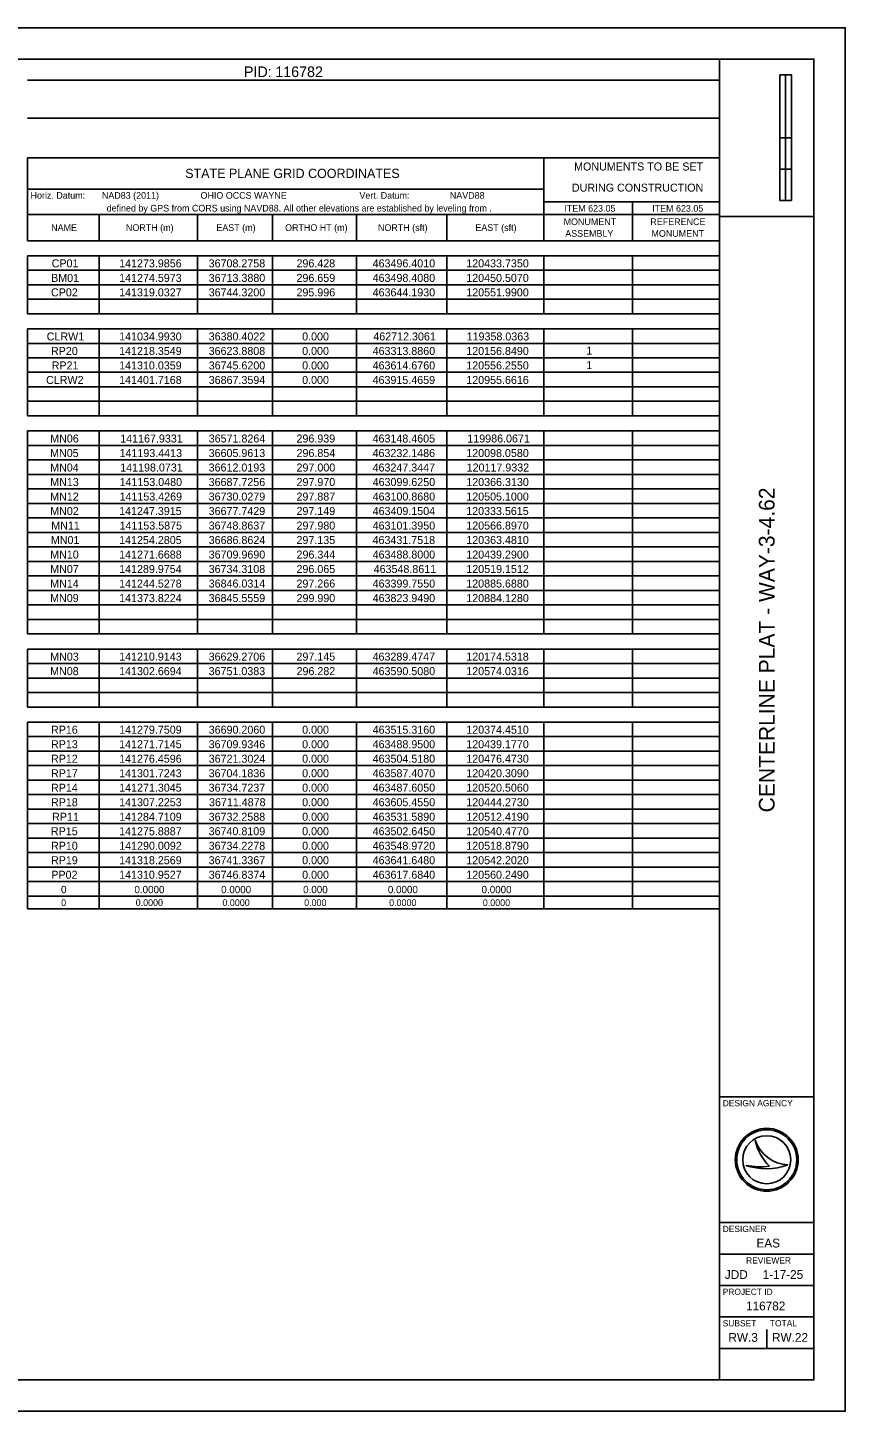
# Model space of a CAD drawing. Extents: x 0 to 34, y 0 to 22.
# Drawn here: x 21 to 34, y 0 to 22 of the extents above; entities that cross this region are included whole.
import ezdxf

# ---------------------------------------------------------------- set-up
doc = ezdxf.new("R2010")
doc.units = 0
for name, color, linetype in [('SH_Border', 7, 'Continuous'), ('SH_Cut_Line', 7, 'Continuous'), ('SH_Data', 7, 'Continuous'), ('SH_Text', 7, 'Continuous')]:
    doc.layers.add(name, color=color, linetype=linetype)

msp = doc.modelspace()

# ---------------------------------------------------------------- linework, layer by layer
at = {"layer": 'SH_Border'}
for p, q in [((32, 0.5), (32, 21.5)), ((32, 19), (33.5, 19)), ((32, 5), (33.5, 5)), ((32, 3), (33.5, 3)), ((32, 2.5), (33.5, 2.5)), ((32, 2), (33.5, 2)), ((32, 1.5), (33.5, 1.5)), ((32, 1), (33.5, 1))]:
    msp.add_line(p, q, dxfattribs=at)
msp.add_lwpolyline([(1.5, 21.5), (33.5, 21.5), (33.5, 0.5), (1.5, 0.5)], close=True, dxfattribs=at)
at = {"layer": 'SH_Cut_Line'}
msp.add_lwpolyline([(0, 0), (34, 0), (34, 22), (0, 22)], close=True, dxfattribs=at)
at = {"layer": 'SH_Data'}
for p, q in [((32.957, 19.25), (32.957, 21.25)), ((33.144, 21.25), (32.957, 21.25)), ((32.957, 20.25), (32.957, 21.25)), ((32.957, 21.25), (33.05, 21.25)), ((33.05, 21.25), (33.051, 21.25)), ((33.051, 21.25), (33.051, 20.25)), ((33.144, 21.25), (33.144, 19.25)), ((33.051, 20.25), (32.957, 20.25)), ((33.143, 20.25), (33.05, 20.25)), ((33.05, 20.25), (33.05, 19.75)), ((33.143, 19.75), (33.143, 20.25)), ((33.05, 19.75), (32.957, 19.75)), ((32.957, 19.75), (32.957, 19.25)), ((33.05, 19.75), (33.143, 19.75)), ((33.05, 19.25), (33.05, 19.75)), ((33.144, 19.25), (32.957, 19.25)), ((32.957, 19.25), (33.05, 19.25)), ((32.567, 4.31), (32.567, 4.31)), ((32.75, 4), (32.75, 4)), ((32.417, 3.91), (32.417, 3.91)), ((33.087, 3.919), (33.087, 3.919)), ((32.75, 1), (32.75, 1.3))]:
    msp.add_line(p, q, dxfattribs=at)
for radius in [0.5, 0.477, 0.477, 0.382]:
    msp.add_circle((32.75, 4), radius, dxfattribs=at)
for centre, radius, start, end in [((33.116, 4.498), 0.58, 198.9257, 198.9319), ((33.347, 4.47), 0.796, 191.6379, 191.6421), ((33.116, 4.498), 0.58, 198.9319, 267.1657), ((33.347, 4.47), 0.796, 191.6421, 226.0947), ((32.739, 4.87), 1.013, 251.4576, 290.0832), ((32.648, 5.154), 1.266, 259.4964, 259.4995), ((32.739, 4.87), 1.013, 251.4527, 251.4576), ((32.648, 5.154), 1.266, 259.4995, 276.6672)]:
    msp.add_arc(centre, radius, start, end, dxfattribs=at)
at = {"layer": 'SH_Text'}
for p, q in [((20.997, 21.168), (22.132, 21.168)), ((22.132, 21.168), (32, 21.168)), ((32, 21.168), (32, 19.932)), ((20.997, 20.559), (22.132, 20.559)), ((22.132, 20.559), (32, 20.559)), ((20.997, 19.932), (22.132, 19.932)), ((20.997, 19.932), (20.997, 19.028)), ((22.132, 19.932), (32, 19.932)), ((29.205, 19.932), (29.205, 19.028)), ((32, 19.932), (32, 19.028)), ((20.997, 19.434), (22.132, 19.434)), ((22.132, 19.434), (29.205, 19.434)), ((29.205, 19.231), (32, 19.231)), ((30.617, 19.231), (30.617, 19.028)), ((20.997, 19.028), (22.132, 19.028)), ((20.997, 19.028), (20.997, 18.613)), ((22.132, 19.028), (32, 19.028)), ((22.132, 19.028), (22.132, 18.613)), ((23.699, 19.028), (23.699, 18.613)), ((24.889, 19.028), (24.889, 18.613)), ((26.226, 19.028), (26.226, 18.613)), ((27.665, 19.028), (27.665, 18.613)), ((29.205, 19.028), (29.205, 18.613)), ((30.617, 19.028), (30.617, 18.613)), ((32, 19.028), (32, 17.451)), ((20.997, 18.613), (22.132, 18.613)), ((22.132, 18.613), (32, 18.613)), ((20.997, 18.373), (22.132, 18.373)), ((20.997, 18.373), (20.997, 17.451)), ((22.132, 18.373), (32, 18.373)), ((22.132, 18.373), (22.132, 17.451)), ((23.699, 18.373), (23.699, 17.451)), ((24.889, 18.373), (24.889, 17.451)), ((26.226, 18.373), (26.226, 17.451)), ((27.665, 18.373), (27.665, 17.451)), ((29.205, 18.373), (29.205, 17.451)), ((30.617, 18.373), (30.617, 17.451)), ((20.997, 18.143), (22.132, 18.143)), ((22.132, 18.143), (32, 18.143)), ((20.997, 17.912), (22.132, 17.912)), ((22.132, 17.912), (32, 17.912)), ((20.997, 17.682), (22.132, 17.682)), ((22.132, 17.682), (32, 17.682)), ((20.997, 17.451), (22.132, 17.451)), ((22.132, 17.451), (32, 17.451)), ((32, 17.451), (32, 17.211)), ((20.997, 17.211), (22.132, 17.211)), ((20.997, 17.211), (20.997, 15.828)), ((22.132, 17.211), (32, 17.211)), ((22.132, 17.211), (22.132, 15.828)), ((23.699, 17.211), (23.699, 15.828)), ((24.889, 17.211), (24.889, 15.828)), ((26.226, 17.211), (26.226, 15.828)), ((27.665, 17.211), (27.665, 15.828)), ((29.205, 17.211), (29.205, 15.828)), ((30.617, 17.211), (30.617, 15.828)), ((32, 17.211), (32, 12.12)), ((20.997, 16.981), (22.132, 16.981)), ((22.132, 16.981), (32, 16.981)), ((20.997, 16.75), (22.132, 16.75)), ((22.132, 16.75), (32, 16.75)), ((20.997, 16.52), (22.132, 16.52)), ((22.132, 16.52), (32, 16.52)), ((20.997, 16.289), (22.132, 16.289)), ((22.132, 16.289), (32, 16.289)), ((20.997, 16.059), (22.132, 16.059)), ((22.132, 16.059), (32, 16.059)), ((20.997, 15.828), (22.132, 15.828)), ((22.132, 15.828), (32, 15.828)), ((20.997, 15.588), (22.132, 15.588)), ((20.997, 15.588), (20.997, 12.36)), ((22.132, 15.588), (32, 15.588)), ((22.132, 15.588), (22.132, 12.36)), ((23.699, 15.588), (23.699, 12.36)), ((24.889, 15.588), (24.889, 12.36)), ((26.226, 15.588), (26.226, 12.36)), ((27.665, 15.588), (27.665, 12.36)), ((29.205, 15.588), (29.205, 12.36)), ((30.617, 15.588), (30.617, 12.36)), ((20.997, 15.358), (22.132, 15.358)), ((22.132, 15.358), (32, 15.358)), ((20.997, 15.127), (22.132, 15.127)), ((22.132, 15.127), (32, 15.127)), ((20.997, 14.896), (22.132, 14.896)), ((22.132, 14.896), (32, 14.896)), ((20.997, 14.666), (22.132, 14.666)), ((22.132, 14.666), (32, 14.666)), ((20.997, 14.435), (22.132, 14.435)), ((22.132, 14.435), (32, 14.435)), ((20.997, 14.205), (22.132, 14.205)), ((22.132, 14.205), (32, 14.205)), ((20.997, 13.974), (22.132, 13.974)), ((22.132, 13.974), (32, 13.974)), ((20.997, 13.744), (22.132, 13.744)), ((22.132, 13.744), (32, 13.744)), ((20.997, 13.513), (22.132, 13.513)), ((22.132, 13.513), (32, 13.513)), ((20.997, 13.282), (22.132, 13.282)), ((22.132, 13.282), (32, 13.282)), ((20.997, 13.052), (22.132, 13.052)), ((22.132, 13.052), (32, 13.052)), ((20.997, 12.821), (22.132, 12.821)), ((22.132, 12.821), (32, 12.821)), ((20.997, 12.591), (22.132, 12.591)), ((22.132, 12.591), (32, 12.591)), ((20.997, 12.36), (22.132, 12.36)), ((22.132, 12.36), (32, 12.36)), ((20.997, 12.12), (22.132, 12.12)), ((20.997, 12.12), (20.997, 11.198)), ((22.132, 12.12), (32, 12.12)), ((22.132, 12.12), (22.132, 11.198)), ((23.699, 12.12), (23.699, 11.198)), ((24.889, 12.12), (24.889, 11.198)), ((26.226, 12.12), (26.226, 11.198)), ((27.665, 12.12), (27.665, 11.198)), ((29.205, 12.12), (29.205, 11.198)), ((30.617, 12.12), (30.617, 11.198)), ((32, 12.12), (32, 10.958)), ((20.997, 11.89), (22.132, 11.89)), ((22.132, 11.89), (32, 11.89)), ((20.997, 11.659), (22.132, 11.659)), ((22.132, 11.659), (32, 11.659)), ((20.997, 11.429), (22.132, 11.429)), ((22.132, 11.429), (32, 11.429)), ((20.997, 11.198), (22.132, 11.198)), ((22.132, 11.198), (32, 11.198)), ((20.997, 10.958), (22.132, 10.958)), ((20.997, 10.958), (20.997, 7.989)), ((22.132, 10.958), (32, 10.958)), ((22.132, 10.958), (22.132, 7.989)), ((23.699, 10.958), (23.699, 7.989)), ((24.889, 10.958), (24.889, 7.989)), ((26.226, 10.958), (26.226, 7.989)), ((27.665, 10.958), (27.665, 7.989)), ((29.205, 10.958), (29.205, 7.989)), ((30.617, 10.958), (30.617, 7.989)), ((32, 10.958), (32, 7.989)), ((20.997, 10.728), (22.132, 10.728)), ((22.132, 10.728), (32, 10.728)), ((20.997, 10.497), (22.132, 10.497)), ((22.132, 10.497), (32, 10.497)), ((20.997, 10.267), (22.132, 10.267)), ((22.132, 10.267), (32, 10.267)), ((20.997, 10.036), (22.132, 10.036)), ((22.132, 10.036), (32, 10.036)), ((20.997, 9.805), (22.132, 9.805)), ((22.132, 9.805), (32, 9.805)), ((20.997, 9.575), (22.132, 9.575)), ((22.132, 9.575), (32, 9.575)), ((20.997, 9.344), (22.132, 9.344)), ((22.132, 9.344), (32, 9.344)), ((20.997, 9.114), (22.132, 9.114)), ((22.132, 9.114), (32, 9.114)), ((20.997, 8.883), (22.132, 8.883)), ((22.132, 8.883), (32, 8.883)), ((20.997, 8.653), (22.132, 8.653)), ((22.132, 8.653), (32, 8.653)), ((20.997, 8.422), (22.132, 8.422)), ((22.132, 8.422), (32, 8.422)), ((20.997, 8.191), (22.132, 8.191)), ((22.132, 8.191), (32, 8.191)), ((20.997, 7.989), (22.132, 7.989)), ((22.132, 7.989), (32, 7.989))]:
    msp.add_line(p, q, dxfattribs=at)

# ---------------------------------------------------------------- texts
at = {"layer": 'SH_Data'}
msp.add_text('CENTERLINE PLAT - WAY-3-4.62', height=0.25, rotation=90, dxfattribs=at).set_placement((32.875, 9.524))
for s, height, p in [('DESIGN AGENCY', 0.1, (32.05, 4.85)), ('DESIGNER', 0.1, (32.05, 2.85)), ('EAS', 0.14, (32.587, 2.605)), ('REVIEWER', 0.1, (32.422, 2.35)), ('JDD', 0.14, (32.084, 2.105)), ('1-17-25', 0.14, (32.685, 2.105)), ('PROJECT ID', 0.1, (32.05, 1.85)), ('116782', 0.14, (32.421, 1.605)), ('SUBSET', 0.1, (32.05, 1.35)), ('TOTAL', 0.1, (32.8, 1.35)), ('RW.3', 0.14, (32.141, 1.105)), ('RW.22', 0.14, (32.834, 1.105))]:
    msp.add_text(s, height=height, dxfattribs=at).set_placement(p)
at = {"layer": 'SH_Text'}
for s, height, p in [('PID:', 0.1697, (24.437, 21.214)), ('116782', 0.1697, (24.935, 21.214)), ('  MONUMENTS TO BE SET', 0.12728, (29.592, 19.729)), ('STATE PLANE GRID COORDINATES', 0.14849, (23.503, 19.609)), ('Horiz. Datum:', 0.10606, (21.043, 19.28)), ('NAD83 (2011)', 0.10606, (22.178, 19.28)), ('OHIO OCCS WAYNE', 0.10606, (23.746, 19.28)), ('Vert. Datum:', 0.10606, (26.273, 19.28)), ('NAVD88', 0.1061, (27.711, 19.28)), (' DURING CONSTRUCTION', 0.12728, (29.604, 19.393)), (' defined by GPS from CORS using NAVD88. All other elevations are established by leveling from .', 0.10606, (22.214, 19.077)), ('ITEM 623.05', 0.10606, (29.532, 19.074)), ('ITEM 623.05', 0.10606, (30.929, 19.074)), ('MONUMENT ', 0.1061, (29.52, 18.861)), ('REFERENCE ', 0.1061, (30.9, 18.861)), ('NAME', 0.1061, (21.371, 18.768)), ('NORTH (m)', 0.1061, (22.56, 18.768)), ('EAST (m)', 0.1061, (23.998, 18.768)), ('ORTHO HT (m)', 0.10606, (25.091, 18.768)), ('NORTH (sft)', 0.10606, (26.568, 18.768)), ('EAST (sft)', 0.1061, (28.117, 18.768)), ('ASSEMBLY', 0.1061, (29.546, 18.675)), ('MONUMENT', 0.1061, (30.917, 18.675)), ('CP01', 0.1273, (21.379, 18.189)), ('141273.9856', 0.12728, (22.452, 18.189)), ('36708.2758', 0.1273, (23.875, 18.189)), ('296.428', 0.1273, (25.272, 18.189)), ('463496.4010', 0.12728, (26.483, 18.189)), ('120433.7350', 0.12728, (27.972, 18.189)), ('BM01', 0.1273, (21.37, 17.958)), ('141274.5973', 0.12728, (22.452, 17.958)), ('36713.3880', 0.1273, (23.876, 17.958)), ('296.659', 0.1273, (25.272, 17.958)), ('463498.4080', 0.12728, (26.483, 17.958)), ('120450.5070', 0.12728, (27.972, 17.958)), ('CP02', 0.1273, (21.368, 17.728)), ('141319.0327', 0.12728, (22.452, 17.728)), ('36744.3200', 0.1273, (23.876, 17.728)), ('295.996', 0.1273, (25.272, 17.728)), ('463644.1930', 0.12728, (26.483, 17.728)), ('120551.9900', 0.12728, (27.972, 17.728)), ('CLRW1', 0.1273, (21.3, 17.027)), ('141034.9930', 0.12728, (22.452, 17.027)), ('36380.4022', 0.1273, (23.876, 17.027)), ('0.000', 0.1273, (25.362, 17.027)), ('462712.3061', 0.12728, (26.494, 17.027)), ('119358.0363', 0.12728, (27.978, 17.027)), ('RP20', 0.1273, (21.368, 16.796)), ('141218.3549', 0.12728, (22.452, 16.796)), ('36623.8808', 0.1273, (23.875, 16.796)), ('0.000', 0.1273, (25.362, 16.796)), ('463313.8860', 0.12728, (26.483, 16.796)), ('120156.8490', 0.12728, (27.972, 16.796)), ('1', 0.127, (29.881, 16.802)), ('RP21', 0.1273, (21.379, 16.566)), ('141310.0359', 0.12728, (22.452, 16.566)), ('36745.6200', 0.1273, (23.876, 16.566)), ('0.000', 0.1273, (25.362, 16.566)), ('463614.6760', 0.12728, (26.483, 16.566)), ('120556.2550', 0.12728, (27.972, 16.566)), ('1', 0.127, (29.881, 16.571)), ('CLRW2', 0.1273, (21.29, 16.335)), ('141401.7168', 0.12728, (22.452, 16.335)), ('36867.3594', 0.1273, (23.876, 16.335)), ('0.000', 0.1273, (25.362, 16.335)), ('463915.4659', 0.12728, (26.482, 16.335)), ('120955.6616', 0.12728, (27.972, 16.335)), ('MN06', 0.1273, (21.355, 15.404)), ('141167.9331', 0.12728, (22.469, 15.404)), ('36571.8264', 0.1273, (23.876, 15.404)), ('296.939', 0.1273, (25.272, 15.404)), ('463148.4605', 0.12728, (26.482, 15.404)), ('119986.0671', 0.12728, (27.989, 15.404)), ('MN05', 0.1273, (21.354, 15.173)), ('141193.4413', 0.12728, (22.458, 15.173)), ('36605.9613', 0.1273, (23.875, 15.173)), ('296.854', 0.1273, (25.273, 15.173)), ('463232.1486', 0.12728, (26.482, 15.173)), ('120098.0580', 0.12728, (27.972, 15.173)), ('MN04', 0.1273, (21.355, 14.943)), ('141198.0731', 0.12728, (22.469, 14.943)), ('36612.0193', 0.1273, (23.875, 14.943)), ('297.000', 0.1273, (25.273, 14.943)), ('463247.3447', 0.12728, (26.482, 14.943)), ('120117.9332', 0.12728, (27.978, 14.943)), ('MN13', 0.1273, (21.355, 14.712)), ('141153.0480', 0.12728, (22.458, 14.712)), ('36687.7256', 0.1273, (23.875, 14.712)), ('297.970', 0.1273, (25.273, 14.712)), ('463099.6250', 0.12728, (26.483, 14.712)), ('120366.3130', 0.12728, (27.972, 14.712)), ('MN12', 0.1273, (21.355, 14.481)), ('141153.4269', 0.12728, (22.458, 14.481)), ('36730.0279', 0.1273, (23.875, 14.481)), ('297.887', 0.1273, (25.272, 14.481)), ('463100.8680', 0.12728, (26.483, 14.481)), ('120505.1000', 0.12728, (27.972, 14.481)), ('MN02', 0.1273, (21.355, 14.251)), ('141247.3915', 0.12728, (22.452, 14.251)), ('36677.7429', 0.1273, (23.875, 14.251)), ('297.149', 0.1273, (25.272, 14.251)), ('463409.1504', 0.12728, (26.483, 14.251)), ('120333.5615', 0.12728, (27.971, 14.251)), ('MN11', 0.1273, (21.372, 14.02)), ('141153.5875', 0.12728, (22.458, 14.02)), ('36748.8637', 0.1273, (23.875, 14.02)), ('297.980', 0.1273, (25.273, 14.02)), ('463101.3950', 0.12728, (26.483, 14.02)), ('120566.8970', 0.12728, (27.972, 14.02)), ('MN01', 0.1273, (21.366, 13.79)), ('141254.2805', 0.12728, (22.452, 13.79)), ('36686.8624', 0.1273, (23.876, 13.79)), ('297.135', 0.1273, (25.272, 13.79)), ('463431.7518', 0.12728, (26.482, 13.79)), ('120363.4810', 0.12728, (27.972, 13.79)), ('MN10', 0.1273, (21.355, 13.559)), ('141271.6688', 0.12728, (22.452, 13.559)), ('36709.9690', 0.1273, (23.876, 13.559)), ('296.344', 0.1273, (25.273, 13.559)), ('463488.8000', 0.12728, (26.483, 13.559)), ('120439.2900', 0.12728, (27.972, 13.559)), ('MN07', 0.1273, (21.355, 13.329)), ('141289.9754', 0.12728, (22.452, 13.329)), ('36734.3108', 0.1273, (23.875, 13.329)), ('296.065', 0.1273, (25.272, 13.329)), ('463548.8611', 0.12728, (26.499, 13.329)), ('120519.1512', 0.12728, (27.973, 13.329)), ('MN14', 0.1273, (21.355, 13.098)), ('141244.5278', 0.12728, (22.452, 13.098)), ('36846.0314', 0.1273, (23.876, 13.098)), ('297.266', 0.1273, (25.272, 13.098)), ('463399.7550', 0.12728, (26.483, 13.098)), ('120885.6880', 0.12728, (27.972, 13.098)), ('MN09', 0.1273, (21.354, 12.867)), ('141373.8224', 0.12728, (22.452, 12.867)), ('36845.5559', 0.1273, (23.875, 12.867)), ('299.990', 0.1273, (25.273, 12.867)), ('463823.9490', 0.12728, (26.483, 12.867)), ('120884.1280', 0.12728, (27.972, 12.867)), ('MN03', 0.1273, (21.355, 11.936)), ('141210.9143', 0.12728, (22.452, 11.936)), ('36629.2706', 0.1273, (23.875, 11.936)), ('297.145', 0.1273, (25.272, 11.936)), ('463289.4747', 0.12728, (26.482, 11.936)), ('120174.5318', 0.12728, (27.972, 11.936)), ('MN08', 0.1273, (21.354, 11.705)), ('141302.6694', 0.12728, (22.452, 11.705)), ('36751.0383', 0.1273, (23.875, 11.705)), ('296.282', 0.1273, (25.273, 11.705)), ('463590.5080', 0.12728, (26.483, 11.705)), ('120574.0316', 0.12728, (27.972, 11.705)), ('RP16', 0.1273, (21.368, 10.774)), ('141279.7509', 0.12728, (22.452, 10.774)), ('36690.2060', 0.1273, (23.876, 10.774)), ('0.000', 0.1273, (25.362, 10.774)), ('463515.3160', 0.12728, (26.483, 10.774)), ('120374.4510', 0.12728, (27.972, 10.774)), ('RP13', 0.1273, (21.368, 10.543)), ('141271.7145', 0.12728, (22.452, 10.543)), ('36709.9346', 0.1273, (23.875, 10.543)), ('0.000', 0.1273, (25.362, 10.543)), ('463488.9500', 0.12728, (26.483, 10.543)), ('120439.1770', 0.12728, (27.972, 10.543)), ('RP12', 0.1273, (21.368, 10.313)), ('141276.4596', 0.12728, (22.452, 10.313)), ('36721.3024', 0.1273, (23.876, 10.313)), ('0.000', 0.1273, (25.362, 10.313)), ('463504.5180', 0.12728, (26.483, 10.313)), ('120476.4730', 0.12728, (27.972, 10.313)), ('RP17', 0.1273, (21.368, 10.082)), ('141301.7243', 0.12728, (22.452, 10.082)), ('36704.1836', 0.1273, (23.875, 10.082)), ('0.000', 0.1273, (25.362, 10.082)), ('463587.4070', 0.12728, (26.483, 10.082)), ('120420.3090', 0.12728, (27.972, 10.082)), ('RP14', 0.1273, (21.368, 9.852)), ('141271.3045', 0.12728, (22.452, 9.852)), ('36734.7237', 0.1273, (23.875, 9.852)), ('0.000', 0.1273, (25.362, 9.852)), ('463487.6050', 0.12728, (26.483, 9.852)), ('120520.5060', 0.12728, (27.972, 9.852)), ('RP18', 0.1273, (21.368, 9.621)), ('141307.2253', 0.12728, (22.452, 9.621)), ('36711.4878', 0.1273, (23.881, 9.621)), ('0.000', 0.1273, (25.362, 9.621)), ('463605.4550', 0.12728, (26.483, 9.621)), ('120444.2730', 0.12728, (27.972, 9.621)), ('RP11', 0.1273, (21.385, 9.39)), ('141284.7109', 0.12728, (22.452, 9.39)), ('36732.2588', 0.1273, (23.875, 9.39)), ('0.000', 0.1273, (25.362, 9.39)), ('463531.5890', 0.12728, (26.483, 9.39)), ('120512.4190', 0.12728, (27.972, 9.39)), ('RP15', 0.1273, (21.367, 9.16)), ('141275.8887', 0.12728, (22.452, 9.16)), ('36740.8109', 0.1273, (23.875, 9.16)), ('0.000', 0.1273, (25.362, 9.16)), ('463502.6450', 0.12728, (26.483, 9.16)), ('120540.4770', 0.12728, (27.972, 9.16)), ('RP10', 0.1273, (21.368, 8.929)), ('141290.0092', 0.12728, (22.453, 8.929)), ('36734.2278', 0.1273, (23.875, 8.929)), ('0.000', 0.1273, (25.362, 8.929)), ('463548.9720', 0.12728, (26.483, 8.929)), ('120518.8790', 0.12728, (27.972, 8.929)), ('RP19', 0.1273, (21.368, 8.699)), ('141318.2569', 0.12728, (22.452, 8.699)), ('36741.3367', 0.1273, (23.875, 8.699)), ('0.000', 0.1273, (25.362, 8.699)), ('463641.6480', 0.12728, (26.483, 8.699)), ('120542.2020', 0.12728, (27.972, 8.699)), ('PP02', 0.1273, (21.373, 8.468)), ('141310.9527', 0.12728, (22.452, 8.468)), ('36746.8374', 0.1273, (23.876, 8.468)), ('0.000', 0.1273, (25.362, 8.468)), ('463617.6840', 0.12728, (26.483, 8.468)), ('120560.2490', 0.12728, (27.972, 8.468)), ('0', 0.117, (21.527, 8.238)), ('0', 0.106, (21.53, 8.035)), ('0.0000', 0.1167, (22.695, 8.238)), ('0.0000', 0.1061, (22.715, 8.035)), ('0.0000', 0.1167, (24.074, 8.238)), ('0.0000', 0.1061, (24.094, 8.035)), ('0.000', 0.1167, (25.378, 8.238)), ('0.000', 0.1061, (25.394, 8.035)), ('0.0000', 0.1167, (26.725, 8.238)), ('0.0000', 0.1061, (26.745, 8.035)), ('0.0000', 0.1167, (28.215, 8.238)), ('0.0000', 0.1061, (28.235, 8.035))]:
    msp.add_text(s, height=height, dxfattribs=at).set_placement(p)

doc.saveas('drawing.dxf')
